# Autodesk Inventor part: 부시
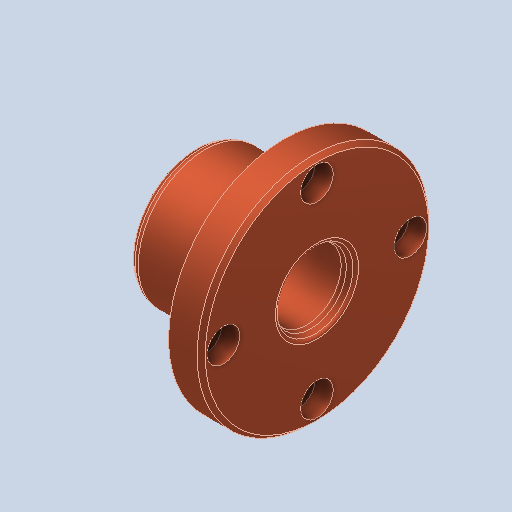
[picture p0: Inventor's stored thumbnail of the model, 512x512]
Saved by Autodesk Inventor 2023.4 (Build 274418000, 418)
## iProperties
Created: 2024-09
Part Number: 부시
Material: 구리, 합금
Document SubType Name: Modeling
Designer: EDU
Density: 8.92 g/cm^3
Appearance: 기본값
Author: jhkim
Sending System: Autodesk Inventor 2025
Preprocessor: ST-DEVELOPER v20
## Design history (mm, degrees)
feature "솔리드1"
node "솔리드2"
